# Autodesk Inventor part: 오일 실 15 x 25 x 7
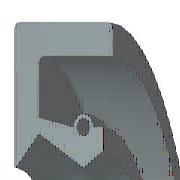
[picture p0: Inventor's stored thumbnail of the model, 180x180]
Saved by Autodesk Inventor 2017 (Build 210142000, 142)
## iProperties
Created: 2012-02
Part Number: 오일 실 15 x 25 x 7
Material: 고무
Description: 오일-실
Document SubType Name: Modeling
Standard: KS B 2804
Designer: mduedu
Standards Organization: KS
Language: ko-KR
Size Designation: D - 15 25 7
Categories: <MemberInstance><Categories><Category DisplayName="샤프트 부품" InternalName="7f7aeb1f-a693-4053-b835-cee3144e0d98" Mnemonic="SHFT"><Category DisplayName="실링" Intern
Density: 0.93 g/cm^3
Appearance: 고무 - 검은색 - 버전 1.1
IsCustomPart: 1
Author: mduedu
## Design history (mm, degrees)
revolve "본체" stored, may be unused: angle "d17" = 90 deg
revolve "스프링1" stored, may be unused: angle "d18" = 90 deg
body "Solid1"
sketch "스케치1"
  geometry: L1 (0, 12.5)-(7, 12.5); L2 (7, 10.75)-(1.75, 10.75); L3 (1.75, 9.25)-(4.9, 7.5); L4 (4.9, 7.5)-(0, 7.5); L5 (0, 0)-(9.586, 0) reference; L6 (4.9, 7.5)-(6.3, 8.375); L7 (0, 18)-(0, -3) reference; L8 (-1.941, 0)-(11.507, 0) reference; L9 (4.2, 9.6)-(1.75, 10.09); L10 (1.75, 10.09)-(1.75, 10.75); L11 (0, 12.5)-(0, 7.588); L12 (4.9, 7.5)-(0, 7.5); L13 (1.75, 9.25)-(0.152, 7.528); L14 (7, 12.5)-(7, 10.75); L15 (5.6, 9.6)-(6.3, 9.6); L16 (6.3, 9.6)-(6.3, 8.375); C1 r 0.455 at (4.9, 9.6); A1 r 0.7 centre (4.9, 9.6) between (5.6, 9.6) and (4.2, 9.6); A2 r 0.088 centre (0.088, 7.588) between (0, 7.588) and (0.152, 7.528); 1 further point
  constraints: 28 end point, 5 horizontal alignment, 5 point on line, 4 point on circle, 4 vertical alignment, 3 centre point, 3 tangent, 2 collinear, 2 horizontal, 2 perpendicular, 1 coincident, 1 parallel
  dimensions: "d0" = 25 diameter of L1 L5 (= SD2); "d1" = 1.75 distance of L1.end L2.start (= SD); "d2" = 0.91 diameter of C1 (= SPDI); "d3" = 1.4 diameter of A1 (= SPDA); "d4" = 15 diameter of L3.end L5 (= NND); "d5" = 18.5 diameter of L3.start L5 (= TKDM); "d7" = 20.18 diameter of L9.end L5 (= TKDM + 0.24 x SWDT); "d8" = 1.75 distance between parallel lines of L11 L10 (= SD); "d9" = 4.9 distance from line of L11 C1.centre (= SPDST); "d10" = 19.2 diameter of C1.centre L5 (= HLDM); "d11" = 0.0875 radius of A2 (= 0.25 x LAB); "d12" = 6.3 distance between parallel lines of L11 L16 (= SDI); "d13" = 16.75 diameter of L6.end L5 (= ABDM); "d14" = 7 distance from line of L11 L1.end (= SWDT)
fillet "모깎기1" dims "d6" = 0.3 (= RR)
other parameters: "SD2" = 25 [user parameter; used in 1 equation term], "SWDT" = 7 [user parameter; used in 2 equation terms], "RR" = 0.3 [user parameter; used in 1 equation term], "SD" = 1.75 [user parameter; used in 2 equation terms], "NND" = 15 [user parameter; used in 1 equation term], "SPDA" = 1.4 [user parameter; used in 1 equation term], "SPDI" = 0.91 [user parameter; used in 1 equation term], "TKDM" = 18.5 [user parameter; used in 2 equation terms], "HLDM" = 19.2 [user parameter; used in 1 equation term], "ABDM" = 16.75 [user parameter; used in 1 equation term], "SDI" = 6.3 [user parameter; used in 1 equation term], "SPDST" = 4.9 [user parameter; used in 1 equation term], "LAB" = 0.35 [user parameter; used in 1 equation term], "d15" = 0, "d16" = 0, "d19" = 0
